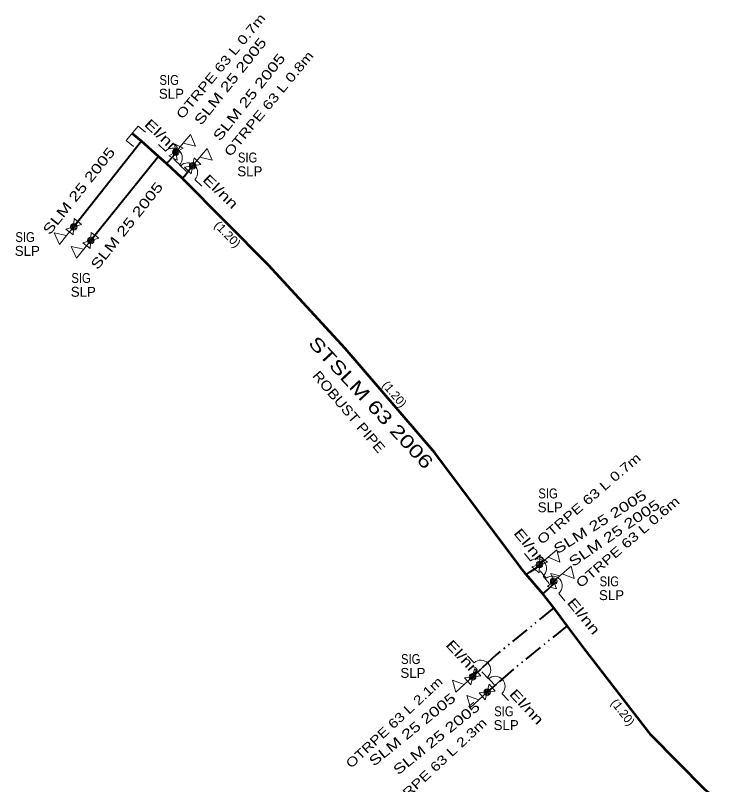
# Model space of a CAD drawing. Extents: x -648036 to -642998, y -1161549 to -1158141.
# Drawn here: x -646593 to -646539.3, y -1161219.3 to -1161161.2 of the extents above; entities that cross this region are included whole.
import ezdxf
from ezdxf.enums import TextEntityAlignment as Align

# ---------------------------------------------------------------- set-up
doc = ezdxf.new("R2010")
doc.units = 0
doc.header["$LTSCALE"] = 0.28
doc.linetypes.add('DASH_DOUBLE_DOT', pattern=[9.2, 5, -1.2, 0.3, -1.2, 0.3, -1.2])
for name, color, linetype, lineweight in [('12', 7, 'DASH_DOUBLE_DOT', 40), ('14', 7, 'Continuous', 13), ('15', 7, 'Continuous', 13), ('19', 7, 'Continuous', 13), ('8', 7, 'Continuous', 53)]:
    doc.layers.add(name, color=color, linetype=linetype, lineweight=lineweight)
for name, color, linetype in [('20', 7, 'Continuous'), ('22', 7, 'Continuous'), ('24', 7, 'Continuous'), ('27', 7, 'Continuous'), ('28', 7, 'Continuous')]:
    doc.layers.add(name, color=color, linetype=linetype)

msp = doc.modelspace()

# ---------------------------------------------------------------- linework, layer by layer
at = {"layer": '12', "linetype": 'Continuous'}
for p, q in [((-646583.42, -1161170.66), (-646588.54, -1161177.14)), ((-646582.14, -1161171.82), (-646587.25, -1161178.18))]:
    msp.add_line(p, q, dxfattribs=at)
for points in [[(-646581.53, -1161172.35), (-646581.38, -1161172.2), (-646581.11, -1161171.9), (-646580.91, -1161171.67), (-646580.82, -1161171.49)], [(-646580.35, -1161173.47), (-646580.2, -1161173.33), (-646579.95, -1161173.01), (-646579.72, -1161172.71), (-646579.55, -1161172.54)], [(-646554.33, -1161203.44), (-646554.02, -1161203.23), (-646553.56, -1161202.94), (-646553.46, -1161202.87), (-646553.32, -1161202.69)], [(-646553.06, -1161204.9), (-646552.72, -1161204.6), (-646552.37, -1161204.25), (-646552.3, -1161204.13), (-646552.25, -1161203.94)]]:
    msp.add_lwpolyline(points, dxfattribs=at)
at = {"layer": '12'}
for points in [[(-646552.25, -1161205.97), (-646556.6, -1161209.51), (-646557.79, -1161210.62), (-646558.16, -1161210.97), (-646558.38, -1161211.17)], [(-646551.24, -1161207.31), (-646555.29, -1161210.6), (-646556.7, -1161211.84), (-646557.05, -1161212.13), (-646557.28, -1161212.33)]]:
    msp.add_lwpolyline(points, dxfattribs=at)
at = {"layer": '14'}
for points in [[(-646581.38, -1161172.2), (-646581.11, -1161171.9), (-646580.91, -1161171.67)], [(-646580.2, -1161173.33), (-646579.95, -1161173.01), (-646579.72, -1161172.71)], [(-646554.02, -1161203.23), (-646553.56, -1161202.94), (-646553.46, -1161202.87)], [(-646552.72, -1161204.6), (-646552.37, -1161204.25), (-646552.3, -1161204.13)], [(-646556.6, -1161209.51), (-646557.79, -1161210.62), (-646558.16, -1161210.97)], [(-646555.29, -1161210.6), (-646556.7, -1161211.84), (-646557.05, -1161212.13)]]:
    msp.add_lwpolyline(points, dxfattribs=at)
at = {"layer": '15'}
for p, q in [((-646582.143, -1161170.919), (-646581.611, -1161171.426)), ((-646580.913, -1161170.88), (-646580.727, -1161172.1)), ((-646580.913, -1161170.88), (-646580.276, -1161171.198)), ((-646580.82, -1161171.49), (-646580.272, -1161170.831)), ((-646580.276, -1161171.198), (-646581.363, -1161171.781)), ((-646581.363, -1161171.781), (-646580.727, -1161172.1)), ((-646580.983, -1161172.029), (-646580.451, -1161172.536)), ((-646579.445, -1161171.932), (-646579.655, -1161173.148)), ((-646579.55, -1161172.54), (-646579.002, -1161171.881)), ((-646579.445, -1161171.932), (-646578.942, -1161172.435)), ((-646580.538, -1161172.453), (-646580.008, -1161172.961)), ((-646578.942, -1161172.435), (-646580.157, -1161172.644)), ((-646580.157, -1161172.644), (-646579.655, -1161173.148)), ((-646579.378, -1161173.563), (-646578.848, -1161174.071)), ((-646588.573, -1161177.756), (-646588.507, -1161176.524)), ((-646587.949, -1161176.966), (-646588.507, -1161176.524)), ((-646589.132, -1161177.315), (-646587.949, -1161176.966)), ((-646588.573, -1161177.756), (-646589.132, -1161177.315)), ((-646588.54, -1161177.14), (-646589.08, -1161177.806)), ((-646587.843, -1161178.35), (-646586.657, -1161178.011)), ((-646587.288, -1161178.796), (-646587.212, -1161177.564)), ((-646586.657, -1161178.011), (-646587.212, -1161177.564)), ((-646587.288, -1161178.796), (-646587.843, -1161178.35)), ((-646587.25, -1161178.18), (-646587.79, -1161178.846)), ((-646554.468, -1161201.842), (-646554.001, -1161202.409)), ((-646552.73, -1161202.511), (-646553.91, -1161202.868)), ((-646553.292, -1161202.074), (-646553.348, -1161203.306)), ((-646553.32, -1161202.69), (-646552.669, -1161202.133)), ((-646553.292, -1161202.074), (-646552.73, -1161202.511)), ((-646553.91, -1161202.868), (-646553.348, -1161203.306)), ((-646553.278, -1161203.152), (-646552.811, -1161203.719)), ((-646553.058, -1161203.558), (-646552.593, -1161204.126)), ((-646551.777, -1161203.543), (-646552.722, -1161204.336)), ((-646552.466, -1161203.362), (-646552.034, -1161204.518)), ((-646552.466, -1161203.362), (-646551.777, -1161203.543)), ((-646552.25, -1161203.94), (-646551.599, -1161203.383)), ((-646552.722, -1161204.336), (-646552.034, -1161204.518)), ((-646551.868, -1161204.868), (-646551.403, -1161205.436)), ((-646558.763, -1161209.578), (-646558.262, -1161210.117)), ((-646558.513, -1161211.772), (-646558.247, -1161210.568)), ((-646557.768, -1161211.095), (-646558.247, -1161210.568)), ((-646558.38, -1161211.17), (-646559.008, -1161211.754)), ((-646558.992, -1161211.246), (-646557.768, -1161211.095)), ((-646557.673, -1161210.798), (-646557.172, -1161211.337)), ((-646557.252, -1161211.206), (-646556.753, -1161211.745)), ((-646558.513, -1161211.772), (-646558.992, -1161211.246)), ((-646557.427, -1161212.929), (-646557.133, -1161211.731)), ((-646556.667, -1161212.269), (-646557.133, -1161211.731)), ((-646557.28, -1161212.33), (-646557.908, -1161212.914)), ((-646557.894, -1161212.392), (-646556.667, -1161212.269)), ((-646557.427, -1161212.929), (-646557.894, -1161212.392)), ((-646556.162, -1161212.426), (-646555.663, -1161212.965))]:
    msp.add_line(p, q, dxfattribs=at)
msp.add_lwpolyline([(-646584.027, -1161171.073), (-646584.57, -1161170.624), (-646583.67, -1161169.536), (-646583.127, -1161169.986)], dxfattribs=at)
for points in [[(-646580.272, -1161170.831), (-646579.335, -1161171.044), (-646579.716, -1161170.162)], [(-646579.002, -1161171.881), (-646578.065, -1161172.094), (-646578.446, -1161171.212)], [(-646589.08, -1161177.806), (-646590.02, -1161177.603), (-646589.628, -1161178.481)], [(-646587.79, -1161178.846), (-646588.73, -1161178.643), (-646588.338, -1161179.521)], [(-646552.669, -1161202.133), (-646551.781, -1161202.501), (-646552.008, -1161201.567)], [(-646551.599, -1161203.383), (-646550.711, -1161203.751), (-646550.938, -1161202.817)], [(-646559.008, -1161211.754), (-646559.91, -1161211.422), (-646559.645, -1161212.346)], [(-646557.908, -1161212.914), (-646558.81, -1161212.582), (-646558.545, -1161213.506)]]:
    msp.add_lwpolyline(points, close=True, dxfattribs=at)
for centre, start, end in [((-646581.0752, -1161171.9397), 317.54741, 136.11212), ((-646579.9152, -1161173.0497), 317.54741, 136.11212), ((-646553.5302, -1161202.9836), 310.67194, 129.23665), ((-646552.3402, -1161204.2936), 310.67194, 129.23665), ((-646557.7576, -1161210.6617), 314.1098, 132.67451), ((-646556.6676, -1161211.8817), 314.1098, 132.67451)]:
    msp.add_arc(centre, 0.7431, start, end, dxfattribs=at)
at = {"layer": '19'}
for centre, radius in [((-646580.82, -1161171.49), 0.25), ((-646580.82, -1161171.49), 0.17), ((-646580.82, -1161171.49), 0.09), ((-646579.55, -1161172.54), 0.25), ((-646579.55, -1161172.54), 0.17), ((-646579.55, -1161172.54), 0.09), ((-646588.54, -1161177.14), 0.25), ((-646588.54, -1161177.14), 0.17), ((-646588.54, -1161177.14), 0.09), ((-646587.25, -1161178.18), 0.25), ((-646587.25, -1161178.18), 0.17), ((-646587.25, -1161178.18), 0.09), ((-646553.32, -1161202.69), 0.25), ((-646553.32, -1161202.69), 0.17), ((-646553.32, -1161202.69), 0.09), ((-646552.25, -1161203.94), 0.25), ((-646552.25, -1161203.94), 0.17), ((-646552.25, -1161203.94), 0.09), ((-646558.38, -1161211.17), 0.25), ((-646558.38, -1161211.17), 0.17), ((-646558.38, -1161211.17), 0.09), ((-646557.28, -1161212.33), 0.25), ((-646557.28, -1161212.33), 0.17), ((-646557.28, -1161212.33), 0.09)]:
    msp.add_circle(centre, radius, dxfattribs=at)
at = {"layer": '8'}
for points in [[(-646554.33, -1161203.44), (-646554.78, -1161202.87), (-646561.24, -1161194.24), (-646568.01, -1161186.34), (-646573.81, -1161180.05), (-646580.35, -1161173.47), (-646581.53, -1161172.35), (-646582.14, -1161171.82), (-646583.42, -1161170.66), (-646584.12, -1161170.08)], [(-646515.28, -1161234.68), (-646515.85, -1161234.53), (-646526.08, -1161230.46), (-646529.98, -1161228.43), (-646535.18, -1161224.46), (-646540.83, -1161219.69), (-646544.89, -1161215.58), (-646549.94, -1161209.03), (-646551.24, -1161207.31), (-646552.25, -1161205.97), (-646553.06, -1161204.9), (-646554.33, -1161203.44)]]:
    msp.add_lwpolyline(points, dxfattribs=at)

# ---------------------------------------------------------------- texts
at = {"layer": '15', "width": 0.85}
for p in [(-646581.3255, -1161166.415), (-646575.3945, -1161172.281), (-646592.2215, -1161178.297), (-646587.9895, -1161181.392), (-646552.6795, -1161197.684), (-646548.0465, -1161204.331), (-646563.0615, -1161210.211), (-646556.0145, -1161214.159)]:
    msp.add_text('SIG', height=0.75, dxfattribs=at).set_placement(p, align=Align.CENTER)
at = {"layer": '15'}
for p in [(-646581.156, -1161167.459), (-646575.225, -1161173.325), (-646592.052, -1161179.341), (-646587.82, -1161182.436), (-646552.51, -1161198.728), (-646547.877, -1161205.375), (-646562.892, -1161211.255), (-646555.845, -1161215.203)]:
    msp.add_text('SLP', height=0.75, dxfattribs=at).set_placement(p, align=Align.CENTER)
at = {"layer": '20', "width": 1.35}
msp.add_text('STSLM 63 2006', height=1, rotation=312.835, dxfattribs=at).set_placement((-646566.4332, -1161190.7751), align=Align.CENTER)
at = {"layer": '22'}
for s, rotation, width, p in [('SLM 25 2005', 51.566, 1.35, (-646576.4097, -1161166.3746)), ('SLM 25 2005', 51.566, 1.35, (-646574.9897, -1161167.5646)), ('SLM 25 2005', 51.566, 1.35, (-646587.8597, -1161174.6646)), ('SLM 25 2005', 51.566, 1.35, (-646584.2397, -1161177.2946)), ('ROBUST PIPE', 310.543, 1.15, (-646568.0246, -1161191.3827)), ('SLM 25 2005', 32.086, 1.35, (-646548.5502, -1161199.7816)), ('SLM 25 2005', 34.377, 1.35, (-646547.4607, -1161200.6208)), ('SLM 25 2005', 38.961, 1.35, (-646562.7118, -1161215.4519)), ('SLM 25 2005', 38.961, 1.35, (-646560.8818, -1161216.1119))]:
    msp.add_text(s, height=0.75, rotation=rotation, dxfattribs=dict(at, width=width)).set_placement(p, align=Align.CENTER)
at = {"layer": '24', "width": 1.3}
for s, rotation, p in [('OTRPE 63 L 0.7m', 50.42, (-646580.32, -1161169.05)), ('OTRPE 63 L 0.8m', 50.42, (-646576.69, -1161171.89)), ('OTRPE 63 L 0.7m', 40.68, (-646553.13, -1161201.21)), ('OTRPE 63 L 0.6m', 40.68, (-646550.2, -1161204.49))]:
    msp.add_text(s, height=0.7, rotation=rotation, dxfattribs=at).set_placement(p)
at = {"layer": '24'}
for s, width, p in [('OTRPE 63 L 2.1m', 1.25, (-646560.5731, -1161211.6209)), ('OTRPE 63 L 2.3m', 1.3, (-646557.2391, -1161214.7408))]:
    msp.add_text(s, height=0.7, rotation=42.972, dxfattribs=dict(at, width=width)).set_placement(p, align=Align.RIGHT)
at = {"layer": '27', "width": 1.05}
msp.add_text('(1.20)', height=0.65, rotation=314.554, dxfattribs=at).set_placement((-646577.1405, -1161177.933), align=Align.CENTER)
at = {"layer": '27'}
for rotation, p in [(310.543, (-646564.5313, -1161190.0047)), (307.678, (-646547.2709, -1161214.0504))]:
    msp.add_text('(1.20)', height=0.65, rotation=rotation, dxfattribs=at).set_placement(p, align=Align.CENTER)
at = {"layer": '28', "width": 1.4}
for rotation, p in [(316.846, (-646580.93, -1161171.6482)), (309.397, (-646553.2926, -1161202.802)), (312.835, (-646558.2899, -1161211.1491))]:
    msp.add_text('El/nn', height=0.75, rotation=rotation, dxfattribs=at).set_placement(p, align=Align.RIGHT)
for rotation, p in [(316.273, (-646578.86, -1161173.64)), (309.397, (-646551.29, -1161205.59)), (312.835, (-646555.66, -1161212.52))]:
    msp.add_text('El/nn', height=0.75, rotation=rotation, dxfattribs=at).set_placement(p)

doc.saveas('drawing.dxf')
